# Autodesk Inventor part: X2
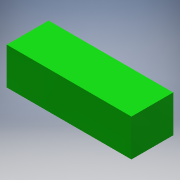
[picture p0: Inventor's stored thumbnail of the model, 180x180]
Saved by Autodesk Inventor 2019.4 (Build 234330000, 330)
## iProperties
Created: 2019-11
Part Number: X2
Material: Generic
Document SubType Name: Modeling
Designer: Willist
Density: 1 g/cm^3
Appearance: MINI, X2
Author: Willist
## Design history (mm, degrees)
sketch "MINI, X2_142"
  geometry: L1 (-6.076, 3.326)-(16, 3.326); L2 (16, 3.326)-(16, -3.25); L3 (16, -3.25)-(-6.076, -3.25); L4 (-6.076, -3.25)-(-6.076, 3.326)
  constraints: 8 end point
extrude "Extrusion1" join sketch "MINI, X2_142" distance "d0" = 1; taper "d1" = 0 deg
sketch "Sketch2"
  geometry: L1 (16, 3.326)-(-6.076, 3.326) reference; L2 (-6.076, -3.25)-(16, -3.25) reference; L3 (-6.076, 3.326)-(16, 3.326); L4 (16, 3.326)-(16, -3.25); L5 (16, -3.25)-(-6.076, -3.25); L6 (-6.076, -3.25)-(-6.076, 3.326); 1 further point
  constraints: 8 end point, 2 parallel, 1 horizontal, 1 perpendicular
extrude "Extrusion2" join sketch "Sketch2" distance "d2" = 6.4; taper "d3" = 0 deg
body "Solid1"
